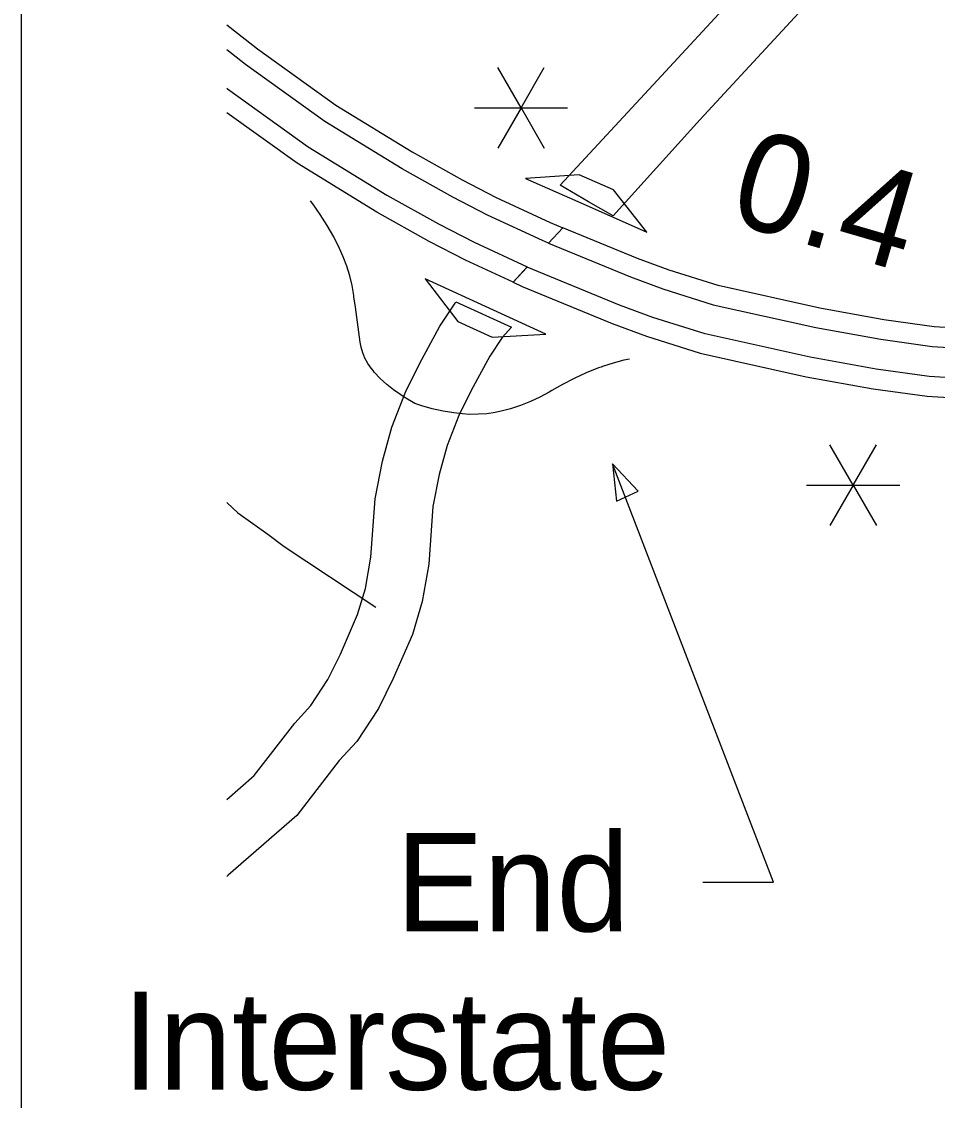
# Model space of a CAD drawing. Extents: x 309348 to 309445, y 336383 to 336484.
# Drawn here: x 309347.661 to 309348.448, y 336396.912 to 336397.84 of the extents above; entities that cross this region are included whole.
import ezdxf

# ---------------------------------------------------------------- set-up
doc = ezdxf.new("R2010")
doc.units = 0
doc.layers.add('R_Annotation', color=7, linetype='Continuous')
doc.layers.add('R_Border Notes', color=7, linetype='Continuous')

msp = doc.modelspace()

# ---------------------------------------------------------------- linework, layer by layer
at = {"layer": 'R_Annotation'}
for p, q in [((309348.09017, 336397.7659), (309348.07016, 336397.80055)), ((309348.09017, 336397.7659), (309348.11018, 336397.80055)), ((309348.05016, 336397.7659), (309348.09017, 336397.7659)), ((309348.09017, 336397.7659), (309348.07016, 336397.73125)), ((309348.09017, 336397.7659), (309348.13018, 336397.7659)), ((309348.09017, 336397.7659), (309348.11018, 336397.73125)), ((309348.14018, 336397.70851), (309348.09409, 336397.70533)), ((309348.16981, 336397.69536), (309348.14018, 336397.70851)), ((309348.09409, 336397.70533), (309348.14623, 336397.68218)), ((309348.19837, 336397.65904), (309348.16981, 336397.69536)), ((309348.14623, 336397.68218), (309348.19837, 336397.65904)), ((309348.12612, 336397.66291), (309348.11379, 336397.64959)), ((309348.12612, 336397.66291), (309348.11379, 336397.64959)), ((309348.09546, 336397.62915), (309348.08332, 336397.61604)), ((309348.09537, 336397.62905), (309348.08332, 336397.61604)), ((309348.0596, 336397.59513), (309348.00776, 336397.61894)), ((309348.00776, 336397.61894), (309348.03585, 336397.58226)), ((309348.11143, 336397.57132), (309348.0596, 336397.59513)), ((309348.03585, 336397.58226), (309348.0653, 336397.56873)), ((309348.0653, 336397.56873), (309348.11143, 336397.57132)), ((309348.37576, 336397.4415), (309348.35576, 336397.47615)), ((309348.37576, 336397.4415), (309348.39577, 336397.47615)), ((309348.33575, 336397.4415), (309348.37576, 336397.4415)), ((309348.37576, 336397.4415), (309348.35576, 336397.40684)), ((309348.37576, 336397.4415), (309348.41578, 336397.4415)), ((309348.37576, 336397.4415), (309348.39577, 336397.40684))]:
    msp.add_line(p, q, dxfattribs=at)
for points in [[(309348.37862, 336397.90145), (309348.24392, 336397.75567), (309348.16933, 336397.67309), (309348.14813, 336397.68515), (309348.12373, 336397.69945), (309348.20714, 336397.78956), (309348.34196, 336397.93548), (309348.44433, 336398.04577), (309348.5005, 336398.10442), (309348.62298, 336398.23632), (309348.63887, 336398.25353), (309348.67593, 336398.21994), (309348.65967, 336398.20234), (309348.53689, 336398.0701), (309348.48072, 336398.01145)], [(309348.17238, 336397.42781), (309348.19091, 336397.43636), (309348.16881, 336397.45988)]]:
    msp.add_lwpolyline(points, close=True, dxfattribs=at)
for points in [[(309347.83713, 336397.83751), (309347.83975, 336397.83526), (309347.86351, 336397.81677), (309347.93085, 336397.76828), (309347.99645, 336397.72808), (309348.03954, 336397.70406), (309348.06875, 336397.68898), (309348.11532, 336397.66736), (309348.12612, 336397.66291)], [(309348.11379, 336397.64959), (309348.10849, 336397.65178), (309348.06127, 336397.6737), (309348.0315, 336397.68908), (309347.98787, 336397.7134), (309347.92142, 336397.75411), (309347.85332, 336397.80315), (309347.83713, 336397.81575)], [(309347.83713, 336397.7828), (309347.83773, 336397.78233), (309347.90701, 336397.73244), (309347.97473, 336397.69094), (309348.0192, 336397.66616), (309348.04982, 336397.65034), (309348.09546, 336397.62915)], [(309348.08332, 336397.61604), (309348.04233, 336397.63507), (309348.01115, 336397.65117), (309347.96615, 336397.67626), (309347.89759, 336397.71827), (309347.83713, 336397.76181)], [(309352.68682, 336397.72903), (309352.18589, 336397.7061), (309351.1163, 336397.66393), (309350.57915, 336397.64505), (309349.68213, 336397.61161), (309349.57437, 336397.60629), (309349.16963, 336397.59333), (309349.09367, 336397.58958), (309348.83801, 336397.58017), (309348.68886, 336397.57601), (309348.50614, 336397.57397), (309348.44551, 336397.57776), (309348.40227, 336397.58375), (309348.34713, 336397.59361), (309348.25975, 336397.61311), (309348.21754, 336397.6264), (309348.19041, 336397.63641), (309348.12612, 336397.66291)], [(309348.11379, 336397.64959), (309348.18422, 336397.62057), (309348.21204, 336397.6103), (309348.25533, 336397.59667), (309348.34378, 336397.57694), (309348.3996, 336397.56695), (309348.44381, 336397.56083), (309348.5057, 336397.55696), (309348.68919, 336397.55901), (309348.83856, 336397.56317), (309349.0944, 336397.57259), (309349.17032, 336397.57634), (309349.57506, 336397.58929), (309349.68287, 336397.59462), (309350.57977, 336397.62805), (309351.11694, 336397.64694), (309352.18661, 336397.68911), (309352.68778, 336397.71205)], [(309347.99894, 336397.51158), (309347.98953, 336397.51725), (309347.98669, 336397.51903), (309347.98051, 336397.52333), (309347.97464, 336397.52807), (309347.96912, 336397.53319), (309347.96397, 336397.5387), (309347.96288, 336397.53996), (309347.96123, 336397.54202), (309347.95839, 336397.54622), (309347.95599, 336397.5507), (309347.95408, 336397.5554), (309347.95267, 336397.56028), (309347.95186, 336397.56458), (309347.94772, 336397.59453), (309347.94651, 336397.60342), (309347.94633, 336397.60466), (309347.94484, 336397.61315), (309347.94283, 336397.62154), (309347.9403, 336397.62978), (309347.93728, 336397.63786), (309347.93415, 336397.64491), (309347.9341, 336397.64502), (309347.92905, 336397.65501), (309347.92352, 336397.66475), (309347.91755, 336397.67422), (309347.91114, 336397.68339), (309347.90901, 336397.68614)], [(309352.68924, 336397.68608), (309352.18772, 336397.66312), (309351.11791, 336397.62095), (309350.58071, 336397.60206), (309349.684, 336397.56863), (309349.57612, 336397.56331), (309349.17137, 336397.55035), (309349.09552, 336397.54661), (309348.8394, 336397.53718), (309348.6897, 336397.533), (309348.50503, 336397.53094), (309348.44122, 336397.53493), (309348.39553, 336397.54126), (309348.33866, 336397.55143), (309348.24858, 336397.57152), (309348.20362, 336397.58569), (309348.17476, 336397.59634), (309348.09537, 336397.62905)], [(309348.08332, 336397.61604), (309348.09123, 336397.61237), (309348.16858, 336397.58049), (309348.19812, 336397.56959), (309348.24417, 336397.55508), (309348.33531, 336397.53476), (309348.39287, 336397.52446), (309348.43952, 336397.518), (309348.5046, 336397.51393), (309348.69003, 336397.516), (309348.83995, 336397.52018), (309349.09625, 336397.52962), (309349.17207, 336397.53336), (309349.57681, 336397.54631), (309349.68473, 336397.55164), (309350.58133, 336397.58507), (309351.11854, 336397.60396), (309352.18844, 336397.64613), (309352.6902, 336397.6691)], [(309348.12612, 336397.66291), (309348.11379, 336397.64959)], [(309348.09537, 336397.62905), (309348.08332, 336397.61604)], [(309347.83713, 336397.17114), (309347.86082, 336397.1918), (309347.89552, 336397.23685), (309347.90935, 336397.25197), (309347.92413, 336397.27431), (309347.93483, 336397.29627), (309347.94966, 336397.33012), (309347.95635, 336397.35273), (309347.96104, 336397.37965), (309347.96462, 336397.42975), (309347.97103, 336397.46225), (309347.9791, 336397.49124), (309347.99077, 336397.52149), (309348.00279, 336397.54582), (309348.02046, 336397.57824), (309348.03359, 336397.59791), (309348.03405, 336397.59925)], [(309348.03405, 336397.59925), (309348.08197, 336397.57738), (309348.07404, 336397.5684), (309348.0633, 336397.55232), (309348.04719, 336397.52277), (309348.03662, 336397.50138), (309348.02664, 336397.47549), (309348.01973, 336397.45068), (309348.01429, 336397.4231), (309348.01075, 336397.37357), (309348.00513, 336397.34129), (309347.99672, 336397.31291), (309347.98023, 336397.27527), (309347.96765, 336397.24945), (309347.9489, 336397.2211), (309347.93385, 336397.20465), (309347.89742, 336397.15735), (309347.83845, 336397.10593), (309347.83713, 336397.10488)], [(309348.18332, 336397.54985), (309348.17855, 336397.54887), (309348.16936, 336397.54646), (309348.16032, 336397.54353), (309348.15904, 336397.54307), (309348.15681, 336397.54225), (309348.14627, 336397.53802), (309348.13594, 336397.53331), (309348.12584, 336397.52811), (309348.11652, 336397.52277), (309348.11426, 336397.52144), (309348.10634, 336397.51716), (309348.09817, 336397.51335), (309348.08979, 336397.51004), (309348.08123, 336397.50723), (309348.07426, 336397.50535), (309348.06803, 336397.50402), (309348.06066, 336397.50295), (309348.05324, 336397.5024), (309348.0458, 336397.50238), (309348.03997, 336397.50274), (309348.03244, 336397.50357), (309348.02311, 336397.50508), (309348.01389, 336397.50711), (309348.00479, 336397.50965), (309347.99894, 336397.51158)], [(309348.24651, 336397.09995), (309348.30732, 336397.09995), (309348.16881, 336397.45988)], [(309347.83713, 336397.42663), (309347.83746, 336397.42626), (309347.84674, 336397.41767), (309347.87235, 336397.39932), (309347.88648, 336397.3888), (309347.96521, 336397.33668)]]:
    msp.add_lwpolyline(points, dxfattribs=at)
at = {"layer": 'R_Border Notes'}
msp.add_line((309347.66068, 336395.72689), (309347.66068, 336403.98769), dxfattribs=at)

# ---------------------------------------------------------------- texts
at = {"layer": 'R_Annotation'}
msp.add_text('0.4', height=0.084508, rotation=343.77473, dxfattribs=at).set_placement((309348.26628, 336397.66872))
for s, p in [('End', (309347.98251, 336397.05769)), ('Interstate', (309347.7474, 336396.92149))]:
    msp.add_text(s, height=0.084508, dxfattribs=at).set_placement(p)

doc.saveas('drawing.dxf')
